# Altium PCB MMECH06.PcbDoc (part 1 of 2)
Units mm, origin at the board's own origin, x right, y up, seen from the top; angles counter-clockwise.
Board outline 65 x 56.01 mm, 4 copper layers (Top Layer, Ground Plane, Mid Layer 1, Bottom Layer), stack 1.442 mm thick; 107 components, 79 nets, 362 pads, 608 vias.
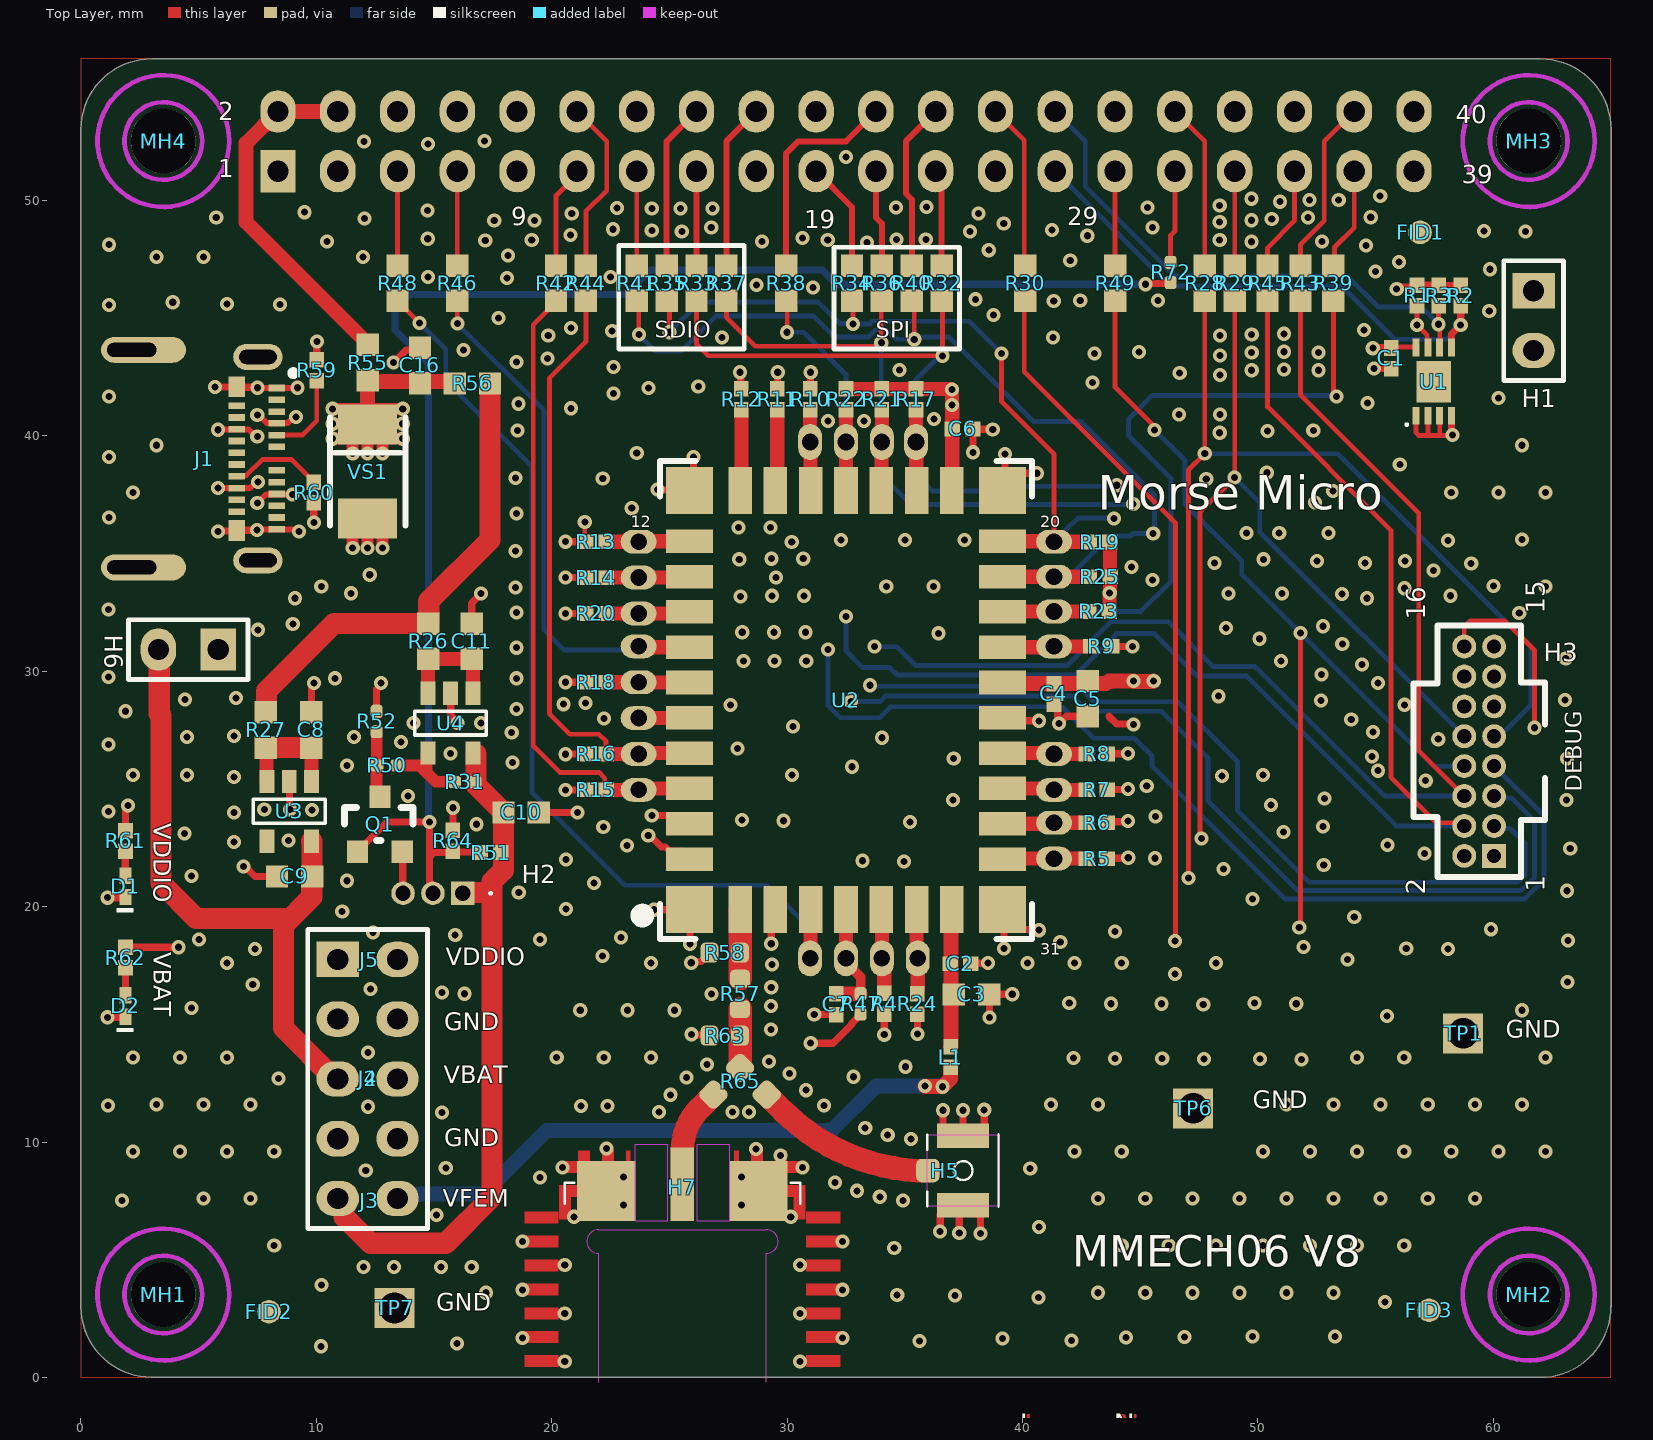
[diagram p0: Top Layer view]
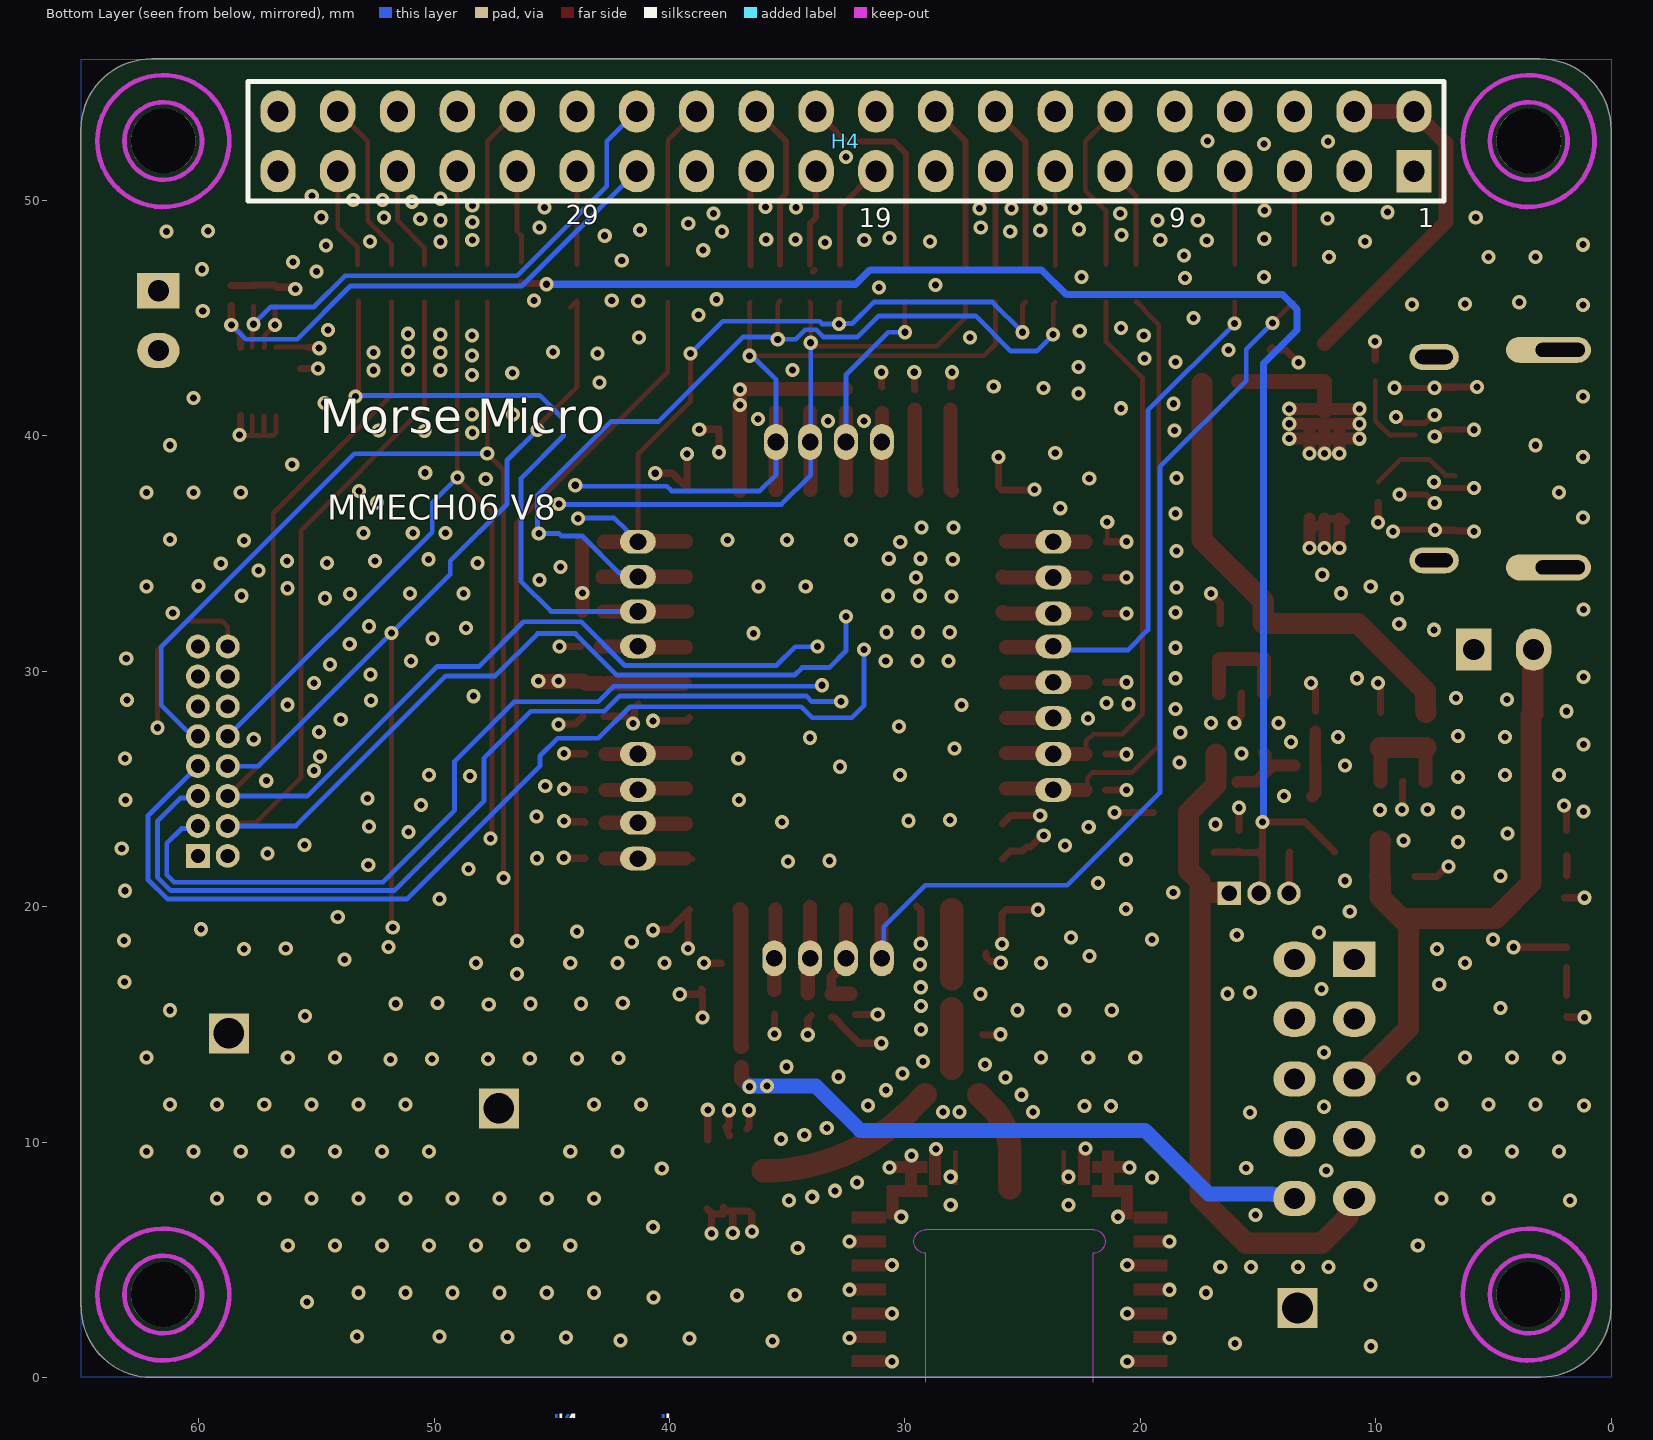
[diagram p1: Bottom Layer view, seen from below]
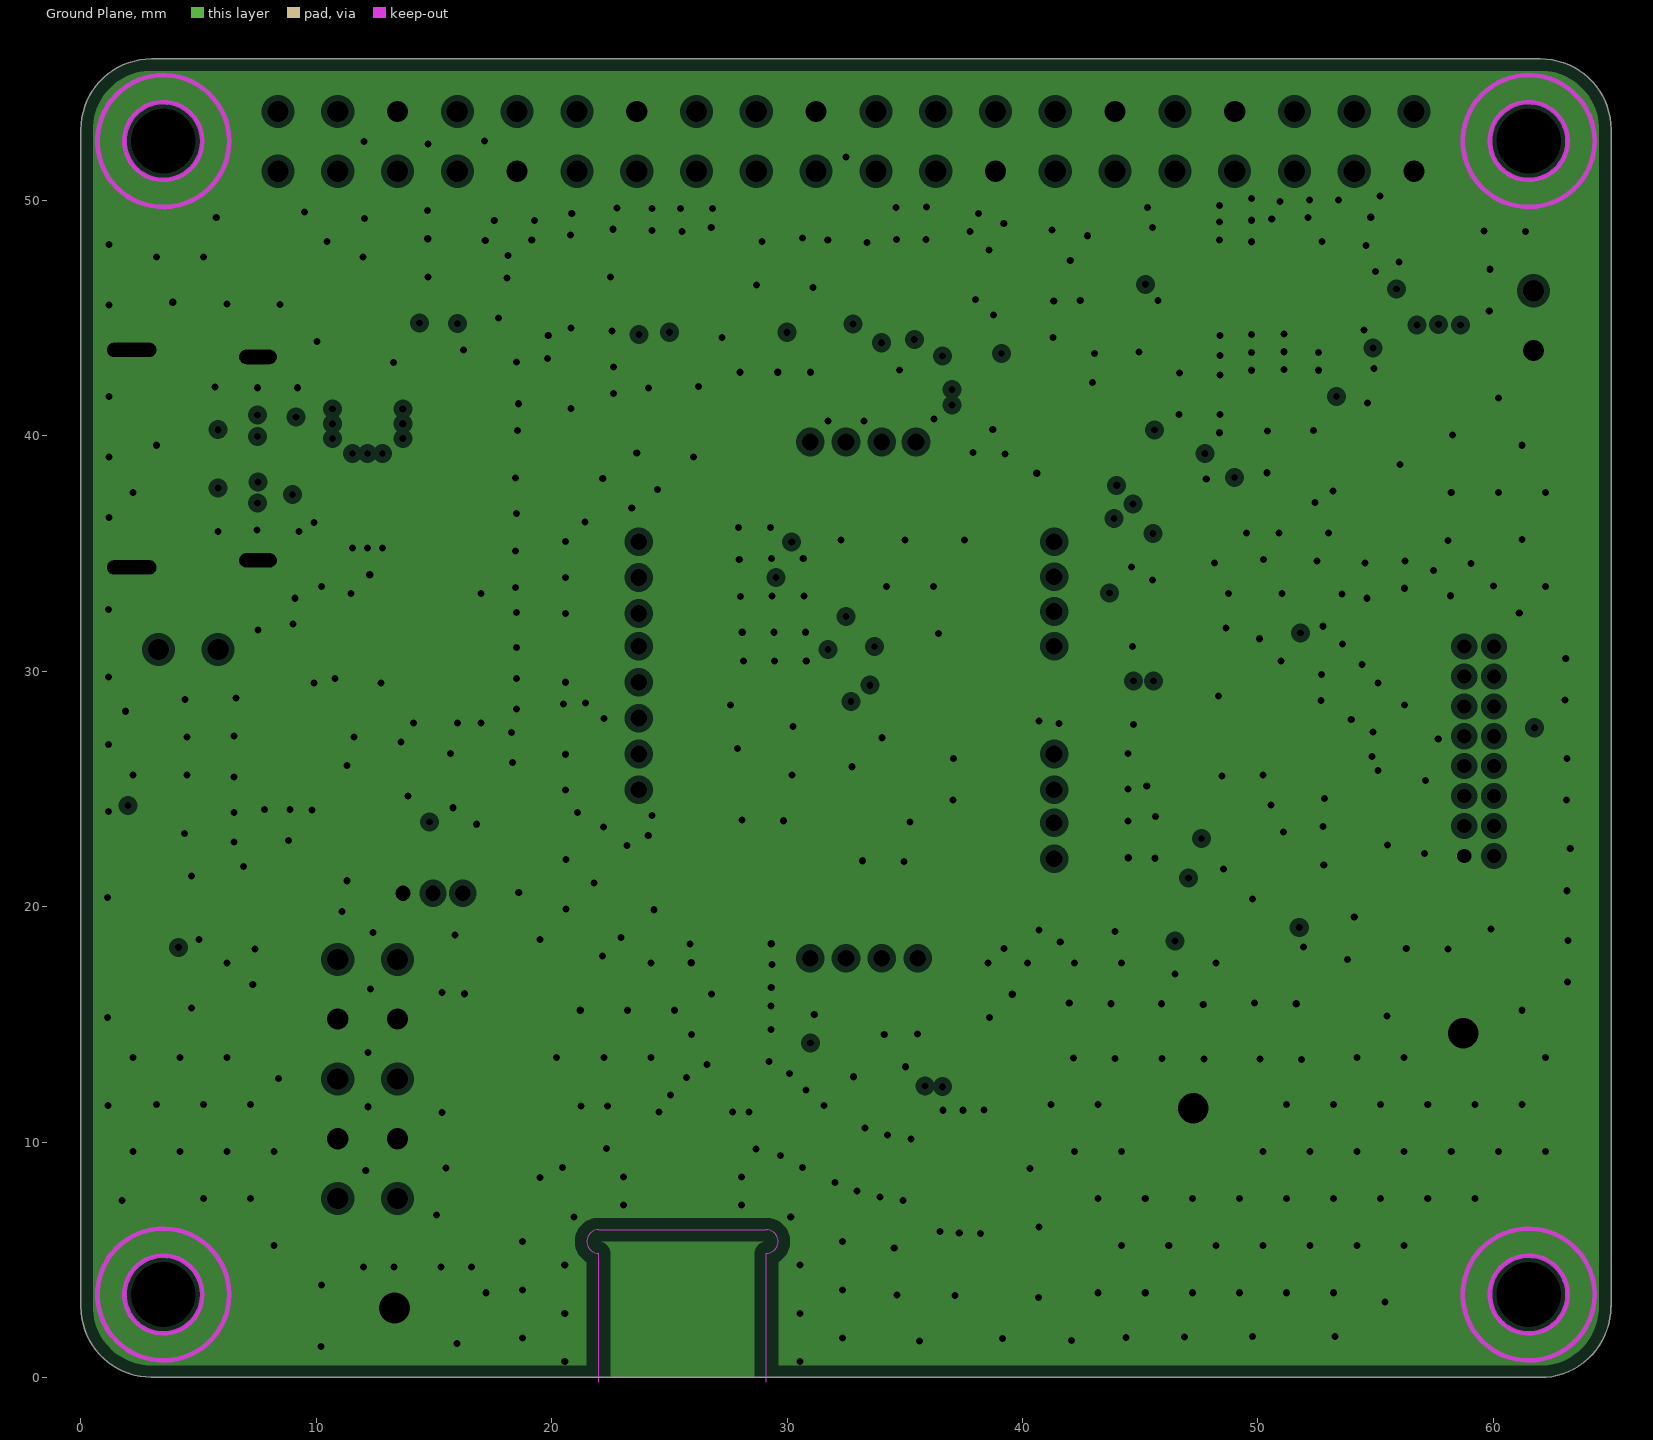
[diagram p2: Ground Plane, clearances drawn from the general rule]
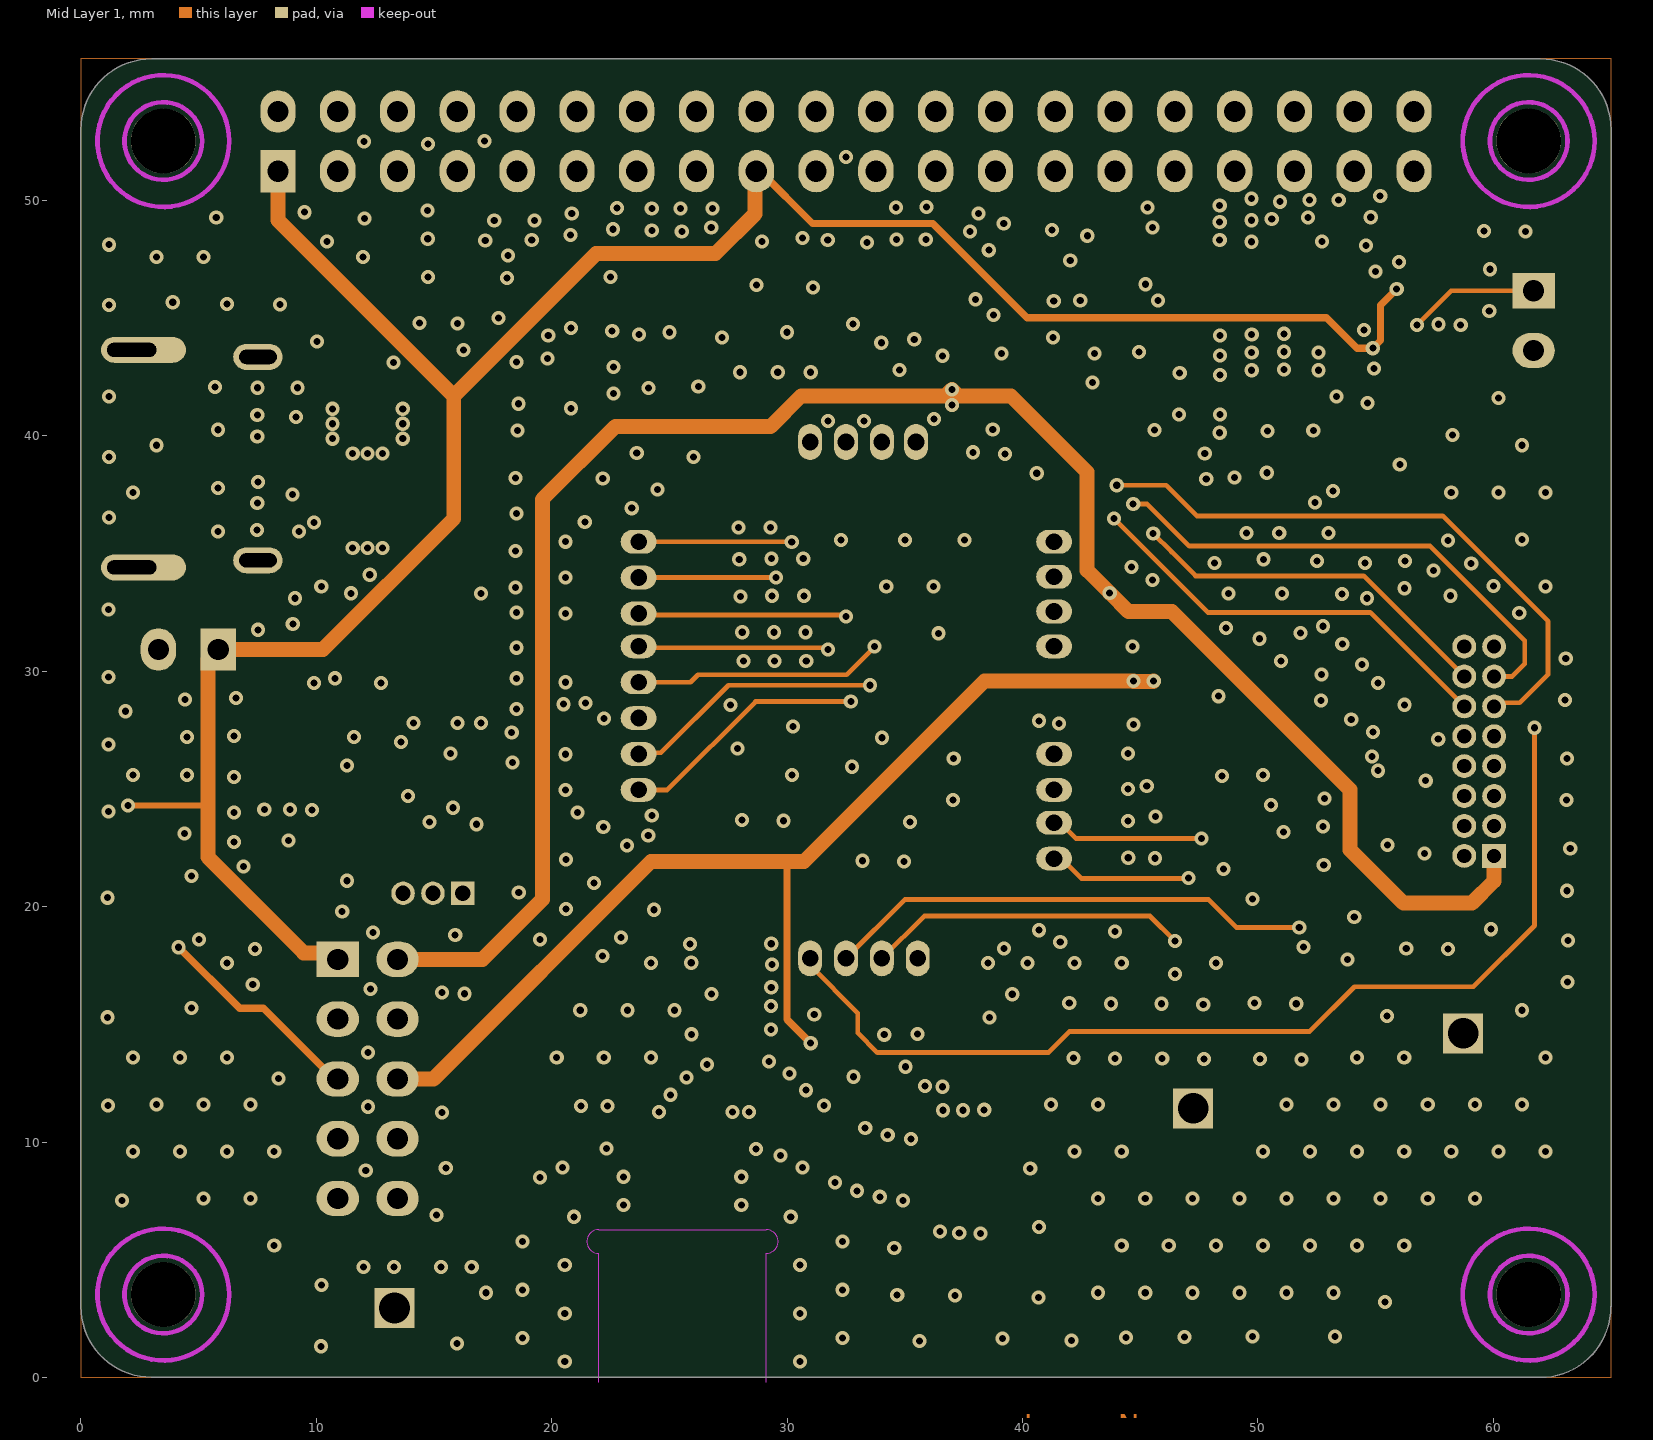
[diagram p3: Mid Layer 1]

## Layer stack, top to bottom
Top Solder: solder mask 0.02, SM-001, Dk 4.2
Top Layer: signal copper 0.035
Dielectric 1: prepreg 0.3048, PP, Dk 4.29
Ground Plane: plane copper 0.035, net GND
Dielectric 2: core 0.692, Core, Dk 4.29
Mid Layer 1: signal copper 0.035
Dielectric 3: prepreg 0.3048, PP, Dk 4.29
Bottom Layer: signal copper 0.035
Bottom Solder: solder mask 0.02, SM-001, Dk 4.2

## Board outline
0,3.011 0,53.011 cw(c3,53.011) 3,56.011 62,56.011 cw(c62,53.011) 65,53.011 65,3.011 64.988,3 cw(c61.988,3) 61.988,0 3.011,0 3,0.011 cw(c3,3.011)

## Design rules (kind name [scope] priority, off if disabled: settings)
AssemblyTestPointUsage [All] p0 off: scope1count=1 scope1_0_kind=Board scope1_0_value=Board scope2count=1 scope2_0_kind=Board scope2_0_value=Board commentlength=0
AssemblyTestPointUsage [All] p1 off:
AssemblyTestpoint [All] p0 off: scope1count=1 scope1_0_kind=Board scope1_0_value=Board scope2count=1 scope2_0_kind=Board scope2_0_value=Board commentlength=0
AssemblyTestpoint [All] p1 off: testpointundercomponent=TRUE minsize=1.016 maxsize=2.54 preferedsize=1.524 minholesize=0 maxholesize=1.016 preferedholesize=0.813 testpointgrid=0.025 usegrid=TRUE gridtolerance=0 allowsidetop=TRUE allowsidebottom=TRUE
BoardOutlineClearance [All] p0 off: scope1count=1 scope1_0_kind=Board scope1_0_value=Board scope2count=1 scope2_0_kind=Board scope2_0_value=Board commentlength=112 gap=0.152 // Protel DXP Scope 1 Expression Was: (not OnTopSilkscreen) AND (NOT OnBottomSilkscreen) and (not OnMultiLayer)
BoardOutlineClearance [(not OnTopSilkscreen) AND (NOT OnBottomSilkscreen) and (not OnMultiLayer)] p1: gap=0.152 ignorepadtopadclearanceinfootprint=FALSE
Clearance [All] p0: scope1count=1 scope1_0_kind=Board scope1_0_value=Board scope2count=1 scope2_0_kind=Board scope2_0_value=Board commentlength=0 gap=0.152
Clearance Clearance_RF [All] p0: scope1count=1 scope1_0_kind=NetClass scope1_0_value=RF-Net scope2count=1 scope2_0_kind=Board scope2_0_value=Board commentlength=0 gap=0.254
Clearance Clearance_RF_Poly [All] p0 off: scope1count=1 scope1_0_kind=Board scope1_0_value=Board scope2count=1 scope2_0_kind=NetClass scope2_0_value=RF-Net commentlength=50 gap=0.255 // Protel DXP Scope 1 Expression Was: (InPolygon)
Clearance "Schematic Clearance Constraint" [All] p0: scope1count=1 scope1_0_kind=Component scope1_0_value=FID1 scope2count=1 scope2_0_kind=Board scope2_0_value=Board commentlength=0 gap=0
Clearance "Schematic Clearance Constraint_1" [All] p0: scope1count=1 scope1_0_kind=Component scope1_0_value=FID2 scope2count=1 scope2_0_kind=Board scope2_0_value=Board commentlength=0 gap=0
Clearance "Schematic Clearance Constraint_2" [All] p0: scope1count=1 scope1_0_kind=Component scope1_0_value=FID3 scope2count=1 scope2_0_kind=Board scope2_0_value=Board commentlength=0 gap=0
Clearance "Schematic Clearance Constraint_2" [InComponent('FID3')] p1: gap=0 ignorepadtopadclearanceinfootprint=FALSE
Clearance "Schematic Clearance Constraint_1" [InComponent('FID2')] p2: gap=0 ignorepadtopadclearanceinfootprint=FALSE
Clearance "Schematic Clearance Constraint" [InComponent('FID1')] p3: gap=0 ignorepadtopadclearanceinfootprint=FALSE
Clearance Clearance_RF_Poly [(InPolygon) vs InNetClass('RF-Net')] p4: gap=0.255 ignorepadtopadclearanceinfootprint=TRUE
Clearance Clearance_RF [InNetClass('RF-Net')] p5: gap=0.254 ignorepadtopadclearanceinfootprint=TRUE
Clearance [All] p6: gap=0.152 ignorepadtopadclearanceinfootprint=TRUE
ComponentClearance [All] p0 off: scope1count=1 scope1_0_kind=Board scope1_0_value=Board scope2count=1 scope2_0_kind=Board scope2_0_value=Board commentlength=0 gap=0.254 collisioncheckmode=3
ComponentClearance [All] p1 off: gap=0.254 collisioncheckmode=3 verticalgap=0.254 showdistances=FALSE
DiffPairsRouting [All] p0 off: scope1count=1 scope1_0_kind=Board scope1_0_value=Board scope2count=1 scope2_0_kind=Board scope2_0_value=Board commentlength=0
DiffPairsRouting [All] p1 off: maxlimit=0.254 minlimit=0.254 mostfreqgap=0.254 toplayer_minwidth=0.381 toplayer_maxwidth=0.381 toplayer_prefwidth=0.381 midlayer3_minwidth=0.381 midlayer3_maxwidth=0.381 midlayer3_prefwidth=0.381 bottomlayer_minwidth=0.381 bottomlayer_maxwidth=0.381 bottomlayer_prefwidth=0.381 maxuncoupledlength=12.7
FabricationTestPointUsage [All] p0 off: scope1count=1 scope1_0_kind=Board scope1_0_value=Board scope2count=1 scope2_0_kind=Board scope2_0_value=Board commentlength=0 valid=0 allowmultiple=FALSE
FabricationTestPointUsage [All] p1 off: valid=0 allowmultiple=FALSE
FabricationTestpoint [All] p0 off: scope1count=1 scope1_0_kind=Board scope1_0_value=Board scope2count=1 scope2_0_kind=Board scope2_0_value=Board commentlength=0 side=3 testpointundercomponent=TRUE minsize=1.016 maxsize=2.54 preferedsize=1.524 minholesize=0 maxholesize=1.016 preferedholesize=0.813 testpointgrid=0.025
FabricationTestpoint [All] p1 off: side=3 testpointundercomponent=TRUE minsize=1.016 maxsize=2.54 preferedsize=1.524 minholesize=0 maxholesize=1.016 preferedholesize=0.813 testpointgrid=0.025 allowsidetop=TRUE allowsidebottom=TRUE usegrid=TRUE gridtolerance=0
FanoutControl Fanout_Default [All] p0 off: scope1count=1 scope1_0_kind=Board scope1_0_value=Board scope2count=1 scope2_0_kind=Board scope2_0_value=Board commentlength=30 // Fanout_Default (Default Rule)
FanoutControl Fanout_Small [All] p0 off: scope1count=1 scope1_0_kind=Board scope1_0_value=Board scope2count=1 scope2_0_kind=Board scope2_0_value=Board commentlength=84 // Protel DXP Scope 1 Expression Was: (CompPinCount < 5)   Fanout_Small (Default Rule)
FanoutControl Fanout_SOIC [All] p0 off: scope1count=1 scope1_0_kind=Board scope1_0_value=Board scope2count=1 scope2_0_kind=Board scope2_0_value=Board commentlength=71 // Protel DXP Scope 1 Expression Was: IsSOIC   Fanout_SOIC (Default Rule)
FanoutControl Fanout_LCC [All] p0 off: scope1count=1 scope1_0_kind=Board scope1_0_value=Board scope2count=1 scope2_0_kind=Board scope2_0_value=Board commentlength=69 // Protel DXP Scope 1 Expression Was: IsLCC   Fanout_LCC (Default Rule)
FanoutControl Fanout_BGA [All] p0 off: scope1count=1 scope1_0_kind=Board scope1_0_value=Board scope2count=1 scope2_0_kind=Board scope2_0_value=Board commentlength=69 // Protel DXP Scope 1 Expression Was: IsBGA   Fanout_BGA (Default Rule)
FanoutControl Fanout_BGA [IsBGA] p1 off: bgadir=Out bgaviamode=Centered fanoutstyle=Auto fanoutdirection=Alternating viagrid=0.025 // Fanout_BGA (Default Rule)
FanoutControl Fanout_LCC [IsLCC] p2 off: bgadir=Out bgaviamode=Centered fanoutstyle=Auto fanoutdirection=Alternating viagrid=0.025 // Fanout_LCC (Default Rule)
FanoutControl Fanout_SOIC [IsSOIC] p3 off: bgadir=Out bgaviamode=Centered fanoutstyle=Auto fanoutdirection=Alternating viagrid=0.025 // Fanout_SOIC (Default Rule)
FanoutControl Fanout_Small [(CompPinCount < 5)] p4 off: bgadir=Out bgaviamode=Centered fanoutstyle=Auto fanoutdirection=OutThenIn viagrid=0.025 // Fanout_Small (Default Rule)
FanoutControl Fanout_Default [All] p5 off: bgadir=Out bgaviamode=Centered fanoutstyle=Auto fanoutdirection=Alternating viagrid=0.025 // Fanout_Default (Default Rule)
Height [All] p0 off: scope1count=1 scope1_0_kind=Board scope1_0_value=Board scope2count=1 scope2_0_kind=Board scope2_0_value=Board commentlength=0
Height "Under Socket" [All] p0 off: scope1count=1 scope1_0_kind=Board scope1_0_value=Board scope2count=1 scope2_0_kind=Board scope2_0_value=Board commentlength=64 // Protel DXP Scope 1 Expression Was: WithinRoom('ROOM_SOCKET')
Height "POGO Pins" [All] p0: scope1count=1 scope1_0_kind=ComponentClass scope1_0_value=POGO scope2count=1 scope2_0_kind=Board scope2_0_value=Board commentlength=0
Height TP1 [All] p0: scope1count=1 scope1_0_kind=Component scope1_0_value=TP1 scope2count=1 scope2_0_kind=Board scope2_0_value=Board commentlength=0
Height TP1 [InComponent('TP1')] p1: minheight=0 maxheight=12 prefheight=3
Height "POGO Pins" [InComponentClass('POGO')] p2: minheight=0 maxheight=7 prefheight=5
Height "Under Socket" [WithinRoom('ROOM_SOCKET')] p3: minheight=0 maxheight=4 prefheight=3
Height [All] p4 off: minheight=0 maxheight=25.4 prefheight=12.7
HoleSize [All] p0: scope1count=1 scope1_0_kind=Board scope1_0_value=Board scope2count=1 scope2_0_kind=Board scope2_0_value=Board commentlength=0 absolutevalues=TRUE maxlimit=5.08 minlimit=0.203 maxpercent=80.000 minpercent=20.000
HoleSize [All] p1: absolutevalues=TRUE maxlimit=5.08 minlimit=0.203 maxpercent=80.000 minpercent=20.000
HoleToHoleClearance [All] p0: scope1count=1 scope1_0_kind=Board scope1_0_value=Board scope2count=1 scope2_0_kind=Board scope2_0_value=Board commentlength=0
HoleToHoleClearance [All] p1: gap=0.203 allowstackedmicrovias=TRUE
LayerPairs [All] p0 off: scope1count=1 scope1_0_kind=Board scope1_0_value=Board scope2count=1 scope2_0_kind=Board scope2_0_value=Board commentlength=0 enforce=TRUE
LayerPairs [All] p1 off: enforce=TRUE
MatchedLengths MatchLengths_U1_Passives_J5 [All] p0 off: scope1count=1 scope1_0_kind=Board scope1_0_value=Board scope2count=1 scope2_0_kind=Board scope2_0_value=Board commentlength=98 tolerance=1.27 amplitude=5.08 gap=0.508 style=90-Degree // Protel DXP Scope 1 Expression Was: InxSignalClass('xSignals_U1_Passives_J5_MatchLengthsClass')
MatchedLengths MatchLengths_U1_Passives_J5_1 [All] p0 off: scope1count=1 scope1_0_kind=Board scope1_0_value=Board scope2count=1 scope2_0_kind=Board scope2_0_value=Board commentlength=100 tolerance=1.27 amplitude=5.08 gap=0.508 style=90-Degree // Protel DXP Scope 1 Expression Was: InxSignalClass('xSignals_U1_Passives_J5_MatchLengthsClass_1')
MatchedLengths MatchLengths_U1_Passives_J5_1 [InxSignalClass('xSignals_U1_Passives_J5_MatchLengthsClass_1')] p1: tolerance=1.27 checknetsindiffpair=FALSE checkdiffpairvsdiffpair=TRUE checkxsignals=TRUE checkothers=TRUE
MatchedLengths MatchLengths_U1_Passives_J5 [InxSignalClass('xSignals_U1_Passives_J5_MatchLengthsClass')] p2: tolerance=1.27 checknetsindiffpair=FALSE checkdiffpairvsdiffpair=TRUE checkxsignals=TRUE checkothers=TRUE
MinimumSolderMaskSliver [All] p0 off: scope1count=1 scope1_0_kind=Board scope1_0_value=Board scope2count=1 scope2_0_kind=Board scope2_0_value=Board commentlength=106 // Protel DXP Scope 1 Expression Was: not InComponent('U4','U1','U5','U6','U7','U8','U9','U10','H2','H3')
MinimumSolderMaskSliver [not InComponent('U4','U1','U5','U6','U7','U8','U9','U10','H2','H3')] p1: minsoldermaskwidth=0.076
NetAntennae [All] p0: scope1count=1 scope1_0_kind=Board scope1_0_value=Board scope2count=1 scope2_0_kind=Board scope2_0_value=Board commentlength=0
PasteMaskExpansion [All] p0: scope1count=1 scope1_0_kind=Board scope1_0_value=Board scope2count=1 scope2_0_kind=Board scope2_0_value=Board commentlength=0 expansion=0
PlaneClearance [All] p0: scope1count=1 scope1_0_kind=Board scope1_0_value=Board scope2count=1 scope2_0_kind=Board scope2_0_value=Board commentlength=0 clearance=0.254
PlaneClearance [All] p1: clearance=0.254
PlaneConnect [All] p0: scope1count=1 scope1_0_kind=Board scope1_0_value=Board scope2count=1 scope2_0_kind=Board scope2_0_value=Board commentlength=0 planeconnectstyle=Relief reliefexpansion=0.508 reliefentries=4 reliefconductorwidth=0.254 reliefairgap=0.254
PlaneConnect PlaneConnect_1 [All] p0 off: scope1count=1 scope1_0_kind=Board scope1_0_value=Board scope2count=1 scope2_0_kind=Board scope2_0_value=Board commentlength=145 planeconnectstyle=Relief reliefexpansion=0.4 reliefentries=4 reliefconductorwidth=0.254 reliefairgap=0.2 // Protel DXP Scope 1 Expression Was: (InComponent('J5') OR InComponent('J6') OR InComponent('J13') OR InComponent('J11') OR InComponent('J12'))
PlaneConnect PlaneConnect_1 [(InComponent('J5') OR InComponent('J6') OR InComponent('J13') OR InComponent('J11') OR InComponent('J12'))] p1: planeconnectstyle=Relief reliefexpansion=0.4 reliefentries=4 reliefconductorwidth=0.254 reliefairgap=0.2
PlaneConnect [All] p2: pad.planeconnectstyle=Relief pad.reliefexpansion=0.508 pad.reliefentries=4 pad.reliefconductorwidth=0.254 pad.reliefairgap=0.254 via.planeconnectstyle=Direct via.reliefexpansion=0.508 via.reliefentries=4 via.reliefconductorwidth=0.254 via.reliefairgap=0.254
PolygonConnect [All] p0: scope1count=1 scope1_0_kind=Board scope1_0_value=Board scope2count=1 scope2_0_kind=Board scope2_0_value=Board commentlength=0 connectstyle=Relief reliefconductorwidth=0.254 reliefentries=4 polygonreliefangle="90 Angle"
PolygonConnect PolygonConnect_1 [All] p0 off: scope1count=1 scope1_0_kind=Net scope1_0_value=GND scope2count=1 scope2_0_kind=Board scope2_0_value=Board commentlength=145 connectstyle=Relief reliefconductorwidth=0.254 reliefentries=4 polygonreliefangle="90 Angle" // Protel DXP Scope 2 Expression Was: (InComponent('J5') OR InComponent('J6') OR InComponent('J13') OR InComponent('J11') OR InComponent('J12'))
PolygonConnect PolygonConnect_1 [InNet('GND') vs (InComponent('J5') OR InComponent('J6') OR InComponent('J13') OR InComponent('J11') OR InComponent('J12'))] p1: connectstyle=Relief reliefconductorwidth=0.254 reliefentries=4 polygonreliefangle="90 Angle" airgapwidth=0.2
PolygonConnect [All] p2: thpad.connectstyle=Relief thpad.reliefconductorwidth=0.254 thpad.reliefentries=4 thpad.polygonreliefangle="90 Angle" thpad.airgapwidth=0.254 smdpad.connectstyle=Direct smdpad.reliefconductorwidth=0.254 smdpad.reliefentries=4 smdpad.polygonreliefangle="90 Angle" smdpad.airgapwidth=0.254 via.connectstyle=Direct via.reliefconductorwidth=0.254 via.reliefentries=4 via.polygonreliefangle="90 Angle" via.airgapwidth=0.254
RoutingCorners [All] p0: scope1count=1 scope1_0_kind=Board scope1_0_value=Board scope2count=1 scope2_0_kind=Board scope2_0_value=Board commentlength=0 cornerstyle=45-Degree minsetback=2.54 maxsetback=2.54
RoutingLayers [All] p0: scope1count=1 scope1_0_kind=Board scope1_0_value=Board scope2count=1 scope2_0_kind=Board scope2_0_value=Board commentlength=0 top layer=Automatic mid layer 3=Automatic bottom layer=Automatic
RoutingPriority [All] p0: scope1count=1 scope1_0_kind=Board scope1_0_value=Board scope2count=1 scope2_0_kind=Board scope2_0_value=Board commentlength=0
RoutingTopology [All] p0: scope1count=1 scope1_0_kind=Board scope1_0_value=Board scope2count=1 scope2_0_kind=Board scope2_0_value=Board commentlength=0 topology=Shortest
RoutingVias [All] p0: scope1count=1 scope1_0_kind=Board scope1_0_value=Board scope2count=1 scope2_0_kind=Board scope2_0_value=Board commentlength=0 holewidth=0.3 width=0.6 viastyle="Through Hole" minholewidth=0.203 minwidth=0.5 maxholewidth=0.711 maxwidth=1.27
RoutingVias [All] p1: holewidth=0.3 width=0.6 viastyle="Through Hole" minholewidth=0.203 minwidth=0.5 maxholewidth=0.711 maxwidth=1.27
ShortCircuit [All] p0: scope1count=1 scope1_0_kind=Board scope1_0_value=Board scope2count=1 scope2_0_kind=Board scope2_0_value=Board commentlength=0 allowed=FALSE
SilkToBoardRegionClearance [All] p0: scope1count=1 scope1_0_kind=Board scope1_0_value=Board scope2count=1 scope2_0_kind=Board scope2_0_value=Board commentlength=0
SilkToSilkClearance [All] p0 off: scope1count=1 scope1_0_kind=Board scope1_0_value=Board scope2count=1 scope2_0_kind=Board scope2_0_value=Board commentlength=0
SilkToSilkClearance [All] p1 off: silktosilkclearance=0.203
SilkToSolderMaskClearance [All] p0 off: scope1count=1 scope1_0_kind=Board scope1_0_value=Board scope2count=1 scope2_0_kind=Board scope2_0_value=Board commentlength=44 // Protel DXP Scope 1 Expression Was: IsPad
SilkToSolderMaskClearance [IsPad] p1 off: minsilkscreentomaskgap=0.102 clearancetoexposedcopper=TRUE
SolderMaskExpansion [All] p0: scope1count=1 scope1_0_kind=Board scope1_0_value=Board scope2count=1 scope2_0_kind=Board scope2_0_value=Board commentlength=0 expansion=0.102
SolderMaskExpansion [All] p1: expansion=0.102 istentingtop=FALSE
SupplyNets [All] p0: scope1count=1 scope1_0_kind=Net scope1_0_value=GND scope2count=1 scope2_0_kind=Board scope2_0_value=Board commentlength=0 voltage=0.000
SupplyNets SupplyNets_7 [All] p0: scope1count=1 scope1_0_kind=Net scope1_0_value=VDD_PA scope2count=1 scope2_0_kind=Board scope2_0_value=Board commentlength=0 voltage=4.000
SupplyNets SupplyNets_6 [All] p0: scope1count=1 scope1_0_kind=Net scope1_0_value=VDD_LNA scope2count=1 scope2_0_kind=Board scope2_0_value=Board commentlength=0 voltage=4.000
SupplyNets SupplyNets_5 [All] p0: scope1count=1 scope1_0_kind=Net scope1_0_value=VDD_FEM scope2count=1 scope2_0_kind=Board scope2_0_value=Board commentlength=0 voltage=4.000
SupplyNets SupplyNets_4 [All] p0: scope1count=1 scope1_0_kind=Net scope1_0_value=VDD5_RPi scope2count=1 scope2_0_kind=Board scope2_0_value=Board commentlength=0 voltage=5.000
SupplyNets SupplyNets_3 [All] p0: scope1count=1 scope1_0_kind=Net scope1_0_value=VDD5 scope2count=1 scope2_0_kind=Board scope2_0_value=Board commentlength=0 voltage=5.000
SupplyNets SupplyNets_2 [All] p0: scope1count=1 scope1_0_kind=Net scope1_0_value=VBAT scope2count=1 scope2_0_kind=Board scope2_0_value=Board commentlength=0 voltage=3.300
SupplyNets SupplyNets_1 [All] p0: scope1count=1 scope1_0_kind=Net scope1_0_value=VDD33 scope2count=1 scope2_0_kind=Board scope2_0_value=Board commentlength=0 voltage=3.300
SupplyNets SupplyNets_1 [InNet('VDD33')] p1: voltage=3.300
SupplyNets SupplyNets_2 [InNet('VBAT')] p2: voltage=3.300
SupplyNets SupplyNets_3 [InNet('VDD5')] p3: voltage=5.000
SupplyNets SupplyNets_4 [InNet('VDD5_RPi')] p4: voltage=5.000
SupplyNets SupplyNets_5 [InNet('VDD_FEM')] p5: voltage=4.000
SupplyNets SupplyNets_6 [InNet('VDD_LNA')] p6: voltage=4.000
SupplyNets SupplyNets_7 [InNet('VDD_PA')] p7: voltage=4.000
SupplyNets [InNet('GND')] p8: voltage=0.000
UnConnectedPin [All] p0 off: scope1count=1 scope1_0_kind=Board scope1_0_value=Board scope2count=1 scope2_0_kind=Board scope2_0_value=Board commentlength=0
UnConnectedPin [All] p1 off:
UnRoutedNet [All] p0: scope1count=1 scope1_0_kind=Board scope1_0_value=Board scope2count=1 scope2_0_kind=Board scope2_0_value=Board commentlength=0
UnRoutedNet [All] p1: checkbadconnections=TRUE
UnpouredPolygon [All] p0: scope1count=1 scope1_0_kind=Board scope1_0_value=Board scope2count=1 scope2_0_kind=Board scope2_0_value=Board commentlength=0
Width [All] p0: scope1count=1 scope1_0_kind=Board scope1_0_value=Board scope2count=1 scope2_0_kind=Board scope2_0_value=Board commentlength=0 maxlimit=1.27 minlimit=0.203 preferedwidth=0.203
Width "RF Width" [All] p0: scope1count=1 scope1_0_kind=NetClass scope1_0_value=RF-Net scope2count=1 scope2_0_kind=Board scope2_0_value=Board commentlength=0 maxlimit=1 minlimit=0.178 preferedwidth=0.254
Width "RF Width" [InNetClass('RF-Net')] p1: maxlimit=1 minlimit=0.178 preferedwidth=0.254 toplayer_minwidth=1 toplayer_prefwidth=1 impedanceprofiledriven=TRUE impedanceprofileid={FB8584CB-3844-47FA-94E5-229847F5405A} impedanceprofilevalue=50.000000 minimp=50.000000 maximp=50.000000 favimp=50.000000
Width [All] p2: maxlimit=1.27 minlimit=0.203 preferedwidth=0.203
9 further rules are at their usual default settings.

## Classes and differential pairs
net class RF-Net: NetH5_1 NetH7_1 NetR57_1 NetR57_2
component class CHIP_OTHER: C3 C5 C8 C9 C10 C11 C16 D1 D2 R26 R27 R28 R29 R30 R32 R33 R34 R35 R36 R37 R38 R39 R40 R41 R42 R43 R44 R45 R46 R48 R49 R55 R56 R57 R58 R63 R65
component class MMECH06_Power: C8 C9 C10 C11 C16 D1 D2 FID1 FID2 FID3 H2 H6 J1 J2 J3 J4 J5 MH1 MH2 MH3 MH4 Q1 R26 R27 R31 R50 R51 R52 R55 R56 R59 R60 R61 R62 R64 R72 TP1 TP6 TP7 U3 U4 VS1
component class CHIP_MICRO: C1 C2 C4 C6 C7 L1 R1 R2 R3 R4 R5 R6 R7 R8 R9 R10 R11 R12 R13 R14 R15 R16 R17 R18 R19 R20 R21 R22 R23 R24 R25 R31 R47 R50 R51 R52 R59 R60 R61 R62 R64 R72
component class MMECH06_Module: C1 C2 C3 C4 C5 C6 C7 H1 H3 H4 H5 H7 L1 R1 R2 R3 R4 R5 R6 R7 R8 R9 R10 R11 R12 R13 R14 R15 R16 R17 R18 R19 R20 R21 R22 R23 R24 R25 R28 R29 R30 R32 R33 R34 R35 R36 R37 R38 R39 R40 R41 R42 R43 R44 R45 R46 R47 R48 R49 R57 R58 R63 R65 U1 U2
component class PCB_PATTERN: FID1 FID2 FID3 FID7 FID8 MH1 MH2 MH3 MH4
component class COMP_OTHER: H1 H2 H3 H4 H5 H6 J1 J2 J3 J4 J5 Q1 TP1 TP6 TP7 U1 U2 U3 U4 VS1

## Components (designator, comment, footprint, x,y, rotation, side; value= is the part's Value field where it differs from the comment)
C1 "CAP" CAPC1005X06N 55.665,43.291 r270 top
C2 "CAP" CAPC1005X06N 37.36,17.58 r0 top
C3 "CAP" CAPC1608X06N 37.834,16.271 r0 top
C4 "CAP" CAPC1005X06N 41.334,29.038 r90 top
C5 "CAP" CAPC1608X06N 42.766,28.838 r270 top
C6 "CAP" CAPC1005X06N 37.453,40.29 r0 top
C7 "CAP" CAPC1005X06N 32.094,15.855 r270 top
C8 "CAP" CAPC1608X06N 9.79,27.504 r270 top
C9 "CAP" CAPC1608X06N 9.079,21.281 r0 top
C10 "CAP" CAPC1608X06N 18.7,24 r180 top
C11 "CAP" CAPC1608X06N 16.6,31.275 r270 top
C16 "CAP" CAPC1608X06N 14.402,42.988 r90 top
D1 "LED_G" LED_0402_GREEN 1.893,20.86 r270 top
D2 "LED_G" LED_0402_GREEN 1.893,15.78 r270 top
FID1 "FIDUCIAL" FIDUCIAL_1MM 56.884,48.641 r0 top
FID2 "FIDUCIAL" FIDUCIAL_1MM 7.989,2.794 r0 top
FID3 "FIDUCIAL" FIDUCIAL_1MM 57.265,2.854 r90 top
H1 "HDR_1X2_DNF" HDR1X2_DNF 61.71,46.161 r270 top
H2 "HDR_1X3" HPH1A03UA 16.223,20.567 r180 top
H3 "2X8_FTSH_DV_K" FTSH_108_D_K 59.399,26.603 r90 top
H4 "HDR_2X20" HDR2X20F 8.37,51.241 r0 bottom locked
H5 "U_FL-R-SMT" U_FL-R-SMT 37.476,8.789 r270 top
H6 "HDR_1X2" HDR1X2 5.83,30.921 r180 top
H7 "SM2924" SM2924-Footprint-1 25.552,0.925 r90 top
J1 "CONN RCP USB3.1 TYPEC 24P SMD RA" USB-C_RCP 5.244,39.03 r270 top
J2 "HDR_2X5" HDR2X5 10.91,17.761 r270 top
J3 "QPC02SXGN-RC" QPC02SXGN-RC 12.25,7.5 r0 top
J4 "QPC02SXGN-RC" QPC02SXGN-RC 12.195,12.705 r0 top
J5 "QPC02SXGN-RC" QPC02SXGN-RC 12.25,17.75 r0 top
L1 "IND" INDC1005X06N 36.946,13.613 r270 top
MH1 "MH_300_275_NPTH" MH_300_275_NPTH 3.5,3.522 r0 top
MH2 "MH_300_275_NPTH" MH_300_275_NPTH 61.5,3.522 r0 top
MH3 "MH_300_275_NPTH" MH_300_275_NPTH 61.5,52.522 r0 top
MH4 "MH_300_275_NPTH" MH_300_275_NPTH 3.5,52.522 r0 top
Q1 "MOSFET_NCH_LGD" SOT-23 12.7,23.5 r0 top
R1 "RES" RESC1005X04N 56.757,45.966 r270 top
R2 "RES" RESC1005X04N 58.611,45.958 r270 top
R3 "RES" RESC1005X04N 57.671,45.958 r270 top
R4 "RES" RESC1005X04N 34.124,15.876 r270 top
R5 "RES" RESC1005X04N 43.157,22.04 r0 top
R6 "RES" RESC1005X04N 43.157,23.564 r0 top
R7 "RES" RESC1005X04N 43.157,24.961 r0 top
R8 "RES" RESC1005X04N 43.157,26.485 r0 top
R9 "RES" RESC1005X04N 43.341,31.057 r0 top
R10 "RES" RESC1005X04N 30.976,41.55 r90 top
R11 "RES" RESC1005X04N 29.579,41.55 r90 top
R12 "RES" RESC1005X04N 28.055,41.55 r90 top
R13 "RES" RESC1005X04N 21.879,35.502 r180 top
R14 "RES" RESC1005X04N 21.879,33.978 r180 top
R15 "RES" RESC1005X04N 21.879,24.961 r180 top
R16 "RES" RESC1005X04N 21.879,26.485 r180 top
R17 "RES" RESC1005X04N 35.473,41.55 r270 top
R18 "RES" RESC1005X04N 21.879,29.533 r180 top
R19 "RES" RESC1005X04N 43.27,35.49 r180 top
R20 "RES" RESC1005X04N 21.879,32.454 r180 top
R21 "RES" RESC1005X04N 34.024,41.55 r90 top
R22 "RES" RESC1005X04N 32.5,41.55 r90 top
R23 "RES" RESC1005X04N 43.246,32.539 r0 top
R24 "RES" RESC1005X04N 35.533,15.868 r270 top
R25 "RES" RESC1005X04N 43.276,34.013 r180 top
R26 "RES" RESC1608X06N 14.747,31.275 r90 top
R27 "RES" RESC1608X06N 7.859,27.504 r90 top
R28 "RES" RESC1608X06N 47.74,46.482 r90 top
R29 "RES" RESC1608X06N 49.01,46.482 r90 top
R30 "RES" RESC1608X06N 40.12,46.482 r90 top
R31 "RES" 0402_res_rnd 16.3,25.3 r180 top
R32 "RES_DNF" RESC1608X06N_DNF 36.564,46.482 r270 top
R33 "RES" RESC1608X06N 26.15,46.482 r90 top
R34 "RES_DNF" RESC1608X06N_DNF 32.754,46.482 r270 top
R35 "RES" RESC1608X06N 24.88,46.482 r90 top
R36 "RES_DNF" RESC1608X06N_DNF 34.024,46.482 r270 top
R37 "RES" RESC1608X06N 27.42,46.482 r90 top
R38 "RES" RESC1608X06N 29.96,46.482 r90 top
R39 "RES" RESC1608X06N 53.204,46.482 r90 top
R40 "RES_DNF" RESC1608X06N_DNF 35.294,46.482 r270 top
R41 "RES" RESC1608X06N 23.61,46.482 r90 top
R42 "RES" RESC1608X06N 20.181,46.482 r90 top
R43 "RES" RESC1608X06N 51.804,46.482 r90 top
R44 "RES" RESC1608X06N 21.451,46.482 r90 top
R45 "RES" RESC1608X06N 50.407,46.482 r90 top
R46 "RES" RESC1608X06N 15.99,46.482 r90 top
R47 "RES" 0402_res_rnd 33.12,15.868 r90 top
R48 "RES" RESC1608X06N 13.45,46.482 r90 top
R49 "RES" RESC1608X06N 43.93,46.482 r90 top
R50 "RES" 0402_res_rnd 13,26 r180 top
R51 "RES" RESC1005X04N 17.4,22.3 r180 top
R52 "RES" 0402_res_rnd 12.562,27.867 r90 top
R55 "RES" RESC1608X06N 12.18,43.113 r270 top
R56 "RES" RESC1608X06N 16.625,42.224 r0 top
R57 "RES" RESC1608X06L 28,16.296 r270 top
R58 "RES" RESC1608X06L 27.35,18.046 r0 top
R59 "RES" RESC1005X04N 10.021,42.783 r90 top
R60 "RES" RESC1005X04N 9.894,37.592 r270 top
R61 "RES" RESC1005X04N 1.893,22.793 r90 top
R62 "RES" RESC1005X04N 1.893,17.84 r90 top
R63 "RES" RESC1608X06L 27.35,14.521 r180 top
R64 "RES" RESC1005X04N 15.8,22.8 r90 top
R65 "RES_AC" 0603_RES_AC_RA 27.434,12.58 r225 top
R72 "RES" 0402_res_rnd 46.29,46.938 r90 top
TP1 "TP-BLK" TP-100_BLACK 58.713,14.614 r0 top
TP6 "TP-BLK" TP-100_BLACK 47.244,11.43 r0 top
TP7 "TP-BLK" TP-100_BLACK 13.323,2.953 r0 top
U1 "CAT24C32HU4I-GT3" DFN8 57.468,42.3 r90 top
U2 "MM6108-MF08651-US" MF04 32.5,28.771 r90 top locked
U3 "LDO_REG2_EN" SOT-23_5 8.85,24.05 r270 top
U4 "RT9187C" SOT-23_5 15.7,27.8 r270 top
VS1 "Varistor_Uni" DO-214AC 12.18,38.481 r90 top

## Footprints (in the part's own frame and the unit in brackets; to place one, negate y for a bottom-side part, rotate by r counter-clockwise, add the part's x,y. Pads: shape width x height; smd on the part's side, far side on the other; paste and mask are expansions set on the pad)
0402_res_rnd [mil]
  rrect50% 22x20 smd: 1(-17,0) 2(17,0)
0603_RES_AC_RA [mm]
  rrect50% 1x1 smd: A(-0.8,0) B(0.8,0) C(-0.8,1.6)
CAPC1005X06N [mm] "Chip Capacitor, 2-Leads, Body 1.00x0.50mm, IPC Medium Density"
  rect 0.66x0.62 smd: 1(-0.44,0) 2(0.44,0)
CAPC1608X06N [mm] "Chip Capacitor, 2-Leads, Body 1.60x0.80mm, IPC Medium Density"
  rect 0.95x0.95 smd: 1(-0.75,0) 2(0.75,0)
DFN8 [mm] "8DFN 8-Leads, Body 3.00x2.00mm, Pitch 0.50mm"
  rect 0.75x0.3 smd paste+0 mask+0: 1(-1.45,0.75) 2(-1.45,0.25) 3(-1.45,-0.25) 4(-1.45,-0.75) 5(1.45,-0.75) 6(1.45,-0.25) 7(1.45,0.25) 8(1.45,0.75)
  rect 1.75x1.45 smd paste+0 mask+0: 9(0,0)
  silkscreen extent -1.87,1.1 -1.78,1.2
DO-214AC [mm]
  rect 1.7x2.5 smd: A(-2,0) K(2,0)
  silkscreen extent -2.3,-1.6 2.3,1.6
FIDUCIAL_1MM [mm]
  round 1 smd paste-1 mask+0: 1(0,0)
FTSH_108_D_K [mil]
  rect 40x40 hole 23.62: 1(-175,-25)
  round 40 hole 23.62: 2(-175,25) 3(-125,-25) 4(-125,25) 5(-75,-25) 6(-75,25) 7(-25,-25) 8(-25,25) 9(25,-25) 10(25,25) 11(75,-25) 12(75,25) 13(125,-25) 14(125,25) 15(175,-25) 16(175,25)
  silkscreen extent -210,-110 210,110
HDR1X2 [mm] "Connector; Header; 2 Position"
  rect 1.5x1.8 hole 0.9: 1(0,0)
  oval 1.5x1.8 hole 0.9: 2(2.54,0)
  silkscreen extent -1.27,-1.27 3.81,1.27
HDR1X2_DNF [mm] "Connector; Header; 2 Position"
  rect 1.5x1.8 hole 0.9: 1(0,0)
  oval 1.5x1.8 hole 0.9: 2(2.54,0)
  silkscreen extent -1.27,-1.27 3.81,1.27
HDR2X5 [mm] "Connector; Header; 5x2 Position"
  rect 1.5x1.8 hole 0.9: 1(0,0)
  oval 1.5x1.8 hole 0.9: 2(0,2.54) 3(2.54,0) 4(2.54,2.54) 5(5.08,0) 6(5.08,2.54) 7(7.62,0) 8(7.62,2.54) 9(10.16,0) 10(10.16,2.54)
  silkscreen extent -1.27,-1.27 11.43,3.81
HDR2X20F [mm] "Connector; Header; 20x2 Position Female"
  rect 1.5x1.8 hole 0.9: 1(0,0)
  oval 1.5x1.8 hole 0.9: 2(0,-2.54) 3(2.54,0) 4(2.54,-2.54) 5(5.08,0) 6(5.08,-2.54) 7(7.62,0) 8(7.62,-2.54) 9(10.16,0) 10(10.16,-2.54) 11(12.7,0) 12(12.7,-2.54) 13(15.24,0) 14(15.24,-2.54) 15(17.78,0) 16(17.78,-2.54) 17(20.32,0) 18(20.32,-2.54) 19(22.86,0) 20(22.86,-2.54) 21(25.4,0) 22(25.4,-2.54) 23(27.94,0) 24(27.94,-2.54) 25(30.48,0) 26(30.48,-2.54) 27(33.02,0) 28(33.02,-2.54) 29(35.56,0) 30(35.56,-2.54) 31(38.1,0) 32(38.1,-2.54) 33(40.64,0) 34(40.64,-2.54) 35(43.18,0) 36(43.18,-2.54) 37(45.72,0) 38(45.72,-2.54) 39(48.26,0) 40(48.26,-2.54)
  silkscreen extent -1.27,-3.81 49.53,1.27
HPH1A03UA [mm]
  rect 1x1 hole 0.65: 1(0,0)
  round 1 hole 0.65: 2(1.27,0) 3(2.54,0)
  silkscreen extent -1.23,-0.05 -1.13,0.05
INDC1005X06N [mm] "Chip Inductor, 2-Leads, Body 1.00x0.50mm, IPC Medium Density"
  rect 0.66x0.62 smd: 1(-0.44,0) 2(0.44,0)
LED_0402_GREEN [mm]
  rect 0.7x0.5 smd: A(-0.45,0) K(0.45,0)
  silkscreen extent 0.92,-0.37 1.1,0.35
MF04 [mm]
  rect 2x2 smd: 1(-8.9,6.65) 12(8.9,6.65) 20(8.9,-6.65) 31(-8.9,-6.65)
  rect 1x2 smd: 2(-6.75,6.65) 3(-5.25,6.65) 4(-3.75,6.65) 5(-2.25,6.65) 6(-0.75,6.65) 7(0.75,6.65) 8(2.25,6.65) 9(3.75,6.65) 10(5.25,6.65) 11(6.75,6.65) 21(6.75,-6.65) 22(5.25,-6.65) 23(3.75,-6.65) 24(2.25,-6.65) 25(0.75,-6.65) 26(-0.75,-6.65) 27(-2.25,-6.65) 28(-3.75,-6.65) 29(-5.25,-6.65) 30(-6.75,-6.65)
  rect 2x1 smd: 13(8.9,4.5) 14(8.9,3) 15(8.9,1.5) 16(8.9,0) 17(8.9,-1.5) 18(8.9,-3) 19(8.9,-4.5) 32(-8.9,-4.5) 33(-8.9,-3) 34(-8.9,-1.5) 35(-8.9,0) 36(-8.9,1.5) 37(-8.9,3)
  rect 2x1 smd mask+0: 38(-8.9,4.5)
  silkscreen extent -10.15,-7.9 10.15,8.9
MH_300_275_NPTH [mm] "Non-plated mount hole M2.5 3.00mm diameter"
  round 2.75 hole 2.75 unplated mask+0: 1(0,0)
  Keep-Out Layer circle w0.2: c0,0 r1.65
QPC02SXGN-RC [mm]
RESC1005X04N [mm] "Chip Resistor, 2-Leads, Body 1.00x0.50mm, IPC Medium Density"
  rect 0.66x0.62 smd: 1(-0.44,0) 2(0.44,0)
RESC1608X06L [mm] "Chip Resistor, 2-Leads, Body 1.55x0.80mm, IPC High Density"
  rrect50% 0.75x0.85 smd: 1(-0.65,0) 2(0.65,0)
RESC1608X06N [mm] "Chip Resistor, 2-Leads, Body 1.55x0.80mm, IPC Medium Density"
  rect 0.95x0.95 smd: 1(-0.75,0) 2(0.75,0)
RESC1608X06N_DNF [mm] "Chip Resistor, 2-Leads, Body 1.55x0.80mm, IPC Medium Density"
  rect 0.95x0.95 smd: 1(-0.75,0) 2(0.75,0)
SM2924-Footprint-1 [mm] "Footprint and 3D model for SM2924 component"
  rect 3.12x1 smd: 1(7.29,0)
  rect 2.54x2.47 smd: 2(7.001,-3.238) 2(7.001,3.239)
  Top Layer region: 7.255,2.404 7.255,2.2 8.718,2.2 8.718,2.404
  Top Layer region: 7.763,3.492 8.271,3.492 8.271,4.956 7.763,4.956
  Top Layer region: 8.718,2.912 8.718,3.42 7.255,3.42 7.255,2.912
  Top Layer region: 6.747,3.492 7.255,3.492 7.255,4.956 6.747,4.956
  Top Layer region: 8.718,3.928 8.718,4.436 7.255,4.436 7.255,3.928
  Top Layer region: 7.255,-3.928 7.255,-4.436 8.718,-4.436 8.718,-3.928
  Top Layer region: 6.747,-4.956 7.255,-4.956 7.255,-3.492 6.747,-3.492
  Top Layer region: 7.255,-2.912 7.255,-3.42 8.718,-3.42 8.718,-2.912
  Top Layer region: 7.763,-4.956 8.271,-4.956 8.271,-3.492 7.763,-3.492
  Top Layer region: 8.718,-2.404 8.718,-2.2 7.255,-2.2 7.255,-2.404
  Top Layer region: 5.791,5.235 5.791,4.727 7.254,4.727 7.254,5.235
  Top Layer region: 4.595,5.256 5.103,5.256 5.103,6.719 4.595,6.719
  Top Layer region: 5.611,5.256 6.119,5.256 6.119,6.719 5.611,6.719
  Top Layer region: 3.579,5.256 4.087,5.256 4.087,6.719 3.579,6.719
  Top Layer region: 2.563,5.256 3.071,5.256 3.071,6.719 2.563,6.719
  Top Layer region: 1.547,5.256 2.055,5.256 2.055,6.719 1.547,6.719
  Top Layer region: 0.531,5.256 1.039,5.256 1.039,6.719 0.531,6.719
  Top Layer region: -0.485,5.256 0.023,5.256 0.023,6.719 -0.485,6.719
  Top Layer region: -0.485,-6.719 0.023,-6.719 0.023,-5.256 -0.485,-5.256
  Top Layer region: 0.531,-6.719 1.039,-6.719 1.039,-5.256 0.531,-5.256
  Top Layer region: 1.547,-6.719 2.055,-6.719 2.055,-5.256 1.547,-5.256
  Top Layer region: 2.563,-6.719 3.071,-6.719 3.071,-5.256 2.563,-5.256
  Top Layer region: 3.579,-6.719 4.087,-6.719 4.087,-5.256 3.579,-5.256
  Top Layer region: 5.611,-6.719 6.119,-6.719 6.119,-5.256 5.611,-5.256
  Top Layer region: 4.595,-6.719 5.103,-6.719 5.103,-5.256 4.595,-5.256
  Top Layer region: 7.254,-5.236 7.254,-4.728 5.791,-4.728 5.791,-5.236
  Top Layer keep-out lines w0: 5.73,2 8.977,2 8.977,0.627 5.73,0.627 5.73,2 ; 5.73,-0.627 5.73,-2 8.977,-2 8.977,-0.627 5.73,-0.627
  Keep-Out Layer lines w0.013: -1.131,3.565 4.35,3.565 cw(c4.85,3.565) 5.35,3.565 5.35,-3.565 cw(c4.85,-3.565) 4.35,-3.565 -1.131,-3.565
  silkscreen extent 6.45,-5 7.35,5
SOT-23 [mm]
  rect 0.9x0.95 smd: 1(-0.95,-1.175) 2(0.95,-1.175) 3(0,1.175)
  silkscreen extent -1.51,-0.68 1.41,0.72
SOT-23_5 [mil]
  rect 39x25 smd: 1(-50,37.5) 2(-50,0) 3(-50,-37.5) 4(50,-37.5) 5(50,37.5)
  silkscreen extent -20,-60 20,60
TP-100_BLACK [mm]
  rect 1.7x1.7 hole 1.3: 1(0,0)
U_FL-R-SMT [mm]
  rrect50% 1x1 smd: 1(0,-1.5)
  rect 1.05x2.2 smd: 2(-1.475,0) 3(1.475,0)
  Top Layer keep-out region: -1.5,-1.55 1.5,-1.55 1.5,1.55 -1.5,1.55
  silkscreen extent -1.55,-1.52 1.55,1.5
USB-C_RCP [mm] "CONN RCP USB3.1 TYPEC 24P SMD RA"
  rect 0.28x0.7 smd mask+0: A1(-3,3.085) A2(-2.5,3.085) A3(-2,3.085) A4(-1.5,3.085) A5(-1,3.085) A6(-0.5,3.085) A7(0.5,3.085) A8(1,3.085) A9(1.5,3.085) A10(2,3.085) A11(2.5,3.085) A12(3,3.085) B2(2.25,1.385) B3(1.75,1.385) B4(1.25,1.385) B5(0.75,1.385) B6(0.25,1.385) B7(-0.25,1.385) B8(-0.75,1.385) B9(-1.25,1.385) B10(-1.75,1.385) B11(-2.25,1.385)
  rect 0.88x0.7 smd mask+0: B1(3.05,1.385) B12(-3.05,1.385)
  oval 1.1x2.1 hole 0.6 slot 1.6 at 90 deg: SH1(-4.32,2.275) SH2(4.32,2.275)
  oval 1.1x3.6 hole 0.6 slot 2.1 at 90 deg copper offset 0,0.5: SH3(4.62,-3.085) SH4(-4.62,-3.085)
  silkscreen extent -3.76,3.65 -3.51,3.9

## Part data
C1 C2 C4 C6: library part CAP0084, "Cap,100nF,10V,+/-10%,X7R,0402"
C3 C5 C8 C9 C10 C11 C16: library part CAP0164, "CAP CER 10UF 25V 20% X5R 0603"
C7: library part CAP0086, "CAP CER 2.2UF 6.3V 20% X5R 0402"
D1 D2: library part DIO0046, "LED GREEN 0402 SMD"
FID1 FID2 FID3: library part PAD0013, "1mm Round Fiducial, 0.5mm Space"
H1: library part HDR0098, "Conn Straight Header 2x1 0.100\" 2 POS (DNF)"
H2: library part HDR0169, "CONN HEADER VERT 3POS 1.27MM"
H3: library part HDR0143, "CONN,Vertical FTSH Series,0.05\"16 Pins, Through Hole"
H4: library part HDR0151, "Conn Female Header 20x2 0.100\" 40 POS"
H5: library part CON0012, "U.FL RF Connector"
H6: library part HDR0006, "Conn Straight Header 2x1 0.100\" 2 POS"
H7: library part JCK0138-4, "Wanshih RF SMD SMA connector with 2 GND pillars - Smaller Connector Barrel"
J1: library part CON0045
J2: library part HDR0012, "Conn Straight Header 5x2 0.100\" 10 POS"
J3 J4 J5: library part HDR0170, "CONN JUMPER SHORTING .100\" GOLD"
L1: library part IND0083, "BEAD 60OHMS 2500MA 32 MOHM"
MH1 MH2 MH3 MH4: library part PAD0031, "MH NPTH 3.00mm DIA 2.75mm HOLE"
Q1: library part TSR0024, "MOSFET N-CH 50V 220MA SOT23-3"
R1: library part RES0004, "RES SMD 1Kohm 1% 1/10W Thick film 0402"
R2 R3: library part RES0204, "RES SMD 3.9K OHM 1% 1/16W 0402"
R4 R5 R6 R7 R8 R9 R10 R11 R12 R13 R14 R15 R16 R18 R20 R24: library part RES0002, "RES SMD 10Kohm 1% 1/10W Thick film 0402"
R17 R19 R21 R22 R23 R25: library part RES0086, "Res, 47K Ohms,1/16W, 1%, 0402,SMD RoHS"
R26 R27 R28 R29 R30 R42 R43 R44 R45 R46 R49 R55 R56 R57 R58 R63: library part RES0119, "Res, 0 Ohm, 1/10W,+/-5%,0603 RoHS"
R31: library part RES0284, "RES 82K OHM 1% 1/16W 0402"
R32 R34 R36 R40: library part RES0035, "Update Later"
R33 R35 R37 R38 R39 R41: library part RES0282, "RES SMD 47 OHM 5% 1/10W 0603"
R47: library part RES0044, "Res,100K Ohms,1/16W, 1%, 0402,SMD RoHS"
R48: library part RES0124, "Res, 10K Ohm, 1/10W,+/-1%,0603 RoHS"
R50: library part RES0011, "RES SMD 18.7K 1% 1/10W Thick film 0402"
R51 R64: library part RES0244, "RES SMD 10K OHM 0.1% 1/16W 0402"
R52: library part RES0285, "RES 7.32K OHM 1% 1/16W 0402"
R59 R60: library part RES0094, "Res, 5.1K Ohms, 1/16W, 1%, 0402,SMD"
R61 R62: library part RES0073, "Res, 330 Ohms, 1/16W, 1%, 0402,SMD"
R65: library part RES0281, "Ohms Jumper Chip Resistor 0603 ( 1608 Metric) - RES_AB"
R72: library part RES0240, "RES 1K OHM 0.5% 1/16W 0402"
TP1 TP6 TP7: library part CON0001, "Test Point PCB, BLACK 0.040\"D"
U1: library part ICT0220, "IC EEPROM 32KBIT I2C 1MHZ 8UDFN"
U2: library part MOD0018, "MM61xx-MF08"
U3: library part REG0071, "IC REG LIN 3.3V 600MA TSOT23-5"
U4: library part REG0079, "IC REG LDO ADJ 0.6A SOT23-5"
VS1: library part DIO0056, "TVS DIODE 6V 10.3V DO214AC"

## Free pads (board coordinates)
  oval 1.524x1.016 hole 0.711: 2(23.691,35.502) 3(23.691,33.978) 4(23.691,29.533) 7(23.691,32.454) 9(23.691,31.057) 10(23.691,28.009) 11(23.691,26.485) 12(23.691,24.961) 19(41.341,22.04) 20(41.341,23.564) 21(41.341,24.961) 22(41.341,26.485) 24(41.341,31.057) 25(41.341,34.013) 27(41.341,32.539) 31(41.341,35.502)
  oval 1.016x1.524 hole 0.711: 14(30.976,17.803) 15(32.5,17.803) 16(34.024,17.803) 17(35.548,17.803) 29(32.5,39.739) 30(34.024,39.739) 34(30.976,39.739) 35(35.473,39.739)

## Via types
v1: diameter 0.6, hole 0.3, Top Layer to Bottom Layer, tented both sides, 608 vias

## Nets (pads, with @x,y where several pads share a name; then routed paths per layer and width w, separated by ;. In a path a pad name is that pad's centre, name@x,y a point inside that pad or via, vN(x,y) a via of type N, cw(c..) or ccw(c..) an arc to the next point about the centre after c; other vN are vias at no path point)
5V_USB: C16.1 J1.A4 J1.A9 J1.B4 J1.B9 R55.2 R56.1 VS1.K | length 23.3
  Top Layer w0.254: v1(5.818,37.79) 5.823,37.785 6.624,37.785 J1.B4@6.629,37.78 7.181,37.78 7.433,38.032 v1(7.527,38.032) ; v1(5.83,40.259) 5.841,40.27 6.618,40.27 J1.B9@6.629,40.28 6.642,40.267 7.124,40.267 7.426,39.965 v1(7.493,39.965) ; v1(7.493,37.146) 7.864,37.517 8.316,37.517 8.317,37.518 8.319,37.516 8.992,37.516 v1(8.994,37.514) ; v1(7.493,40.88) 7.56,40.88 7.896,40.543 8.316,40.543 J1.A4@8.329,40.53 8.342,40.543 8.79,40.543 9.05,40.803 v1(9.144,40.803)
  Top Layer w0.508: v1(10.688,39.878) VS1.K@11.545,39.878 ; v1(10.688,40.513) 11.545,40.513 VS1.K@11.926,40.513 ; v1(10.688,41.148) VS1.K@11.926,41.148 ; v1(11.545,39.243) VS1.K@11.545,39.878 ; VS1.K@11.545,40.481 VS1.K@11.545,39.878 ; VS1.K@11.926,39.878 VS1.K@11.545,39.878 ; v1(12.18,39.243) 12.18,39.878 VS1.K@12.18,40.481 ; VS1.K@12.434,39.878 VS1.K@12.815,39.878 ; VS1.K@12.434,40.513 12.815,40.513 v1(13.672,40.513) ; VS1.K@12.434,41.148 v1(13.672,41.148) ; v1(12.815,39.243) VS1.K@12.815,39.878 ; VS1.K@12.815,40.481 VS1.K@12.815,39.878 ; v1(13.672,39.878) VS1.K@12.815,39.878
  Top Layer w0.635: VS1.K@12.18,41.032 12.18,42.313 14.593,42.313 R56.1@15.825,42.313
CC1: J1.A5 R59.1 | length 3.7
  Top Layer w0.203: J1.A5@8.329,40.03 8.98,40.03 9.411,40.03 10.021,40.64 10.021,41.716 R59.1@10.021,42.351
CC2: J1.B5 R60.1 | length 4
  Top Layer w0.203: J1.B5@6.632,38.284 6.667,38.319 7.029,38.319 7.7,38.989 8.954,38.989 9.894,38.049 R60.1@9.894,38.024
